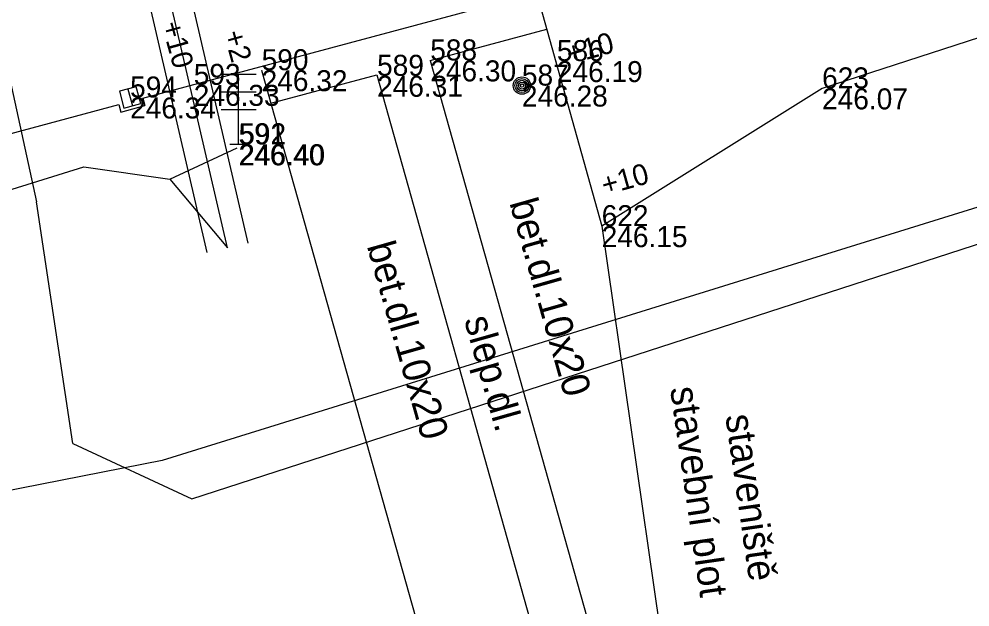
# Model space of a CAD drawing. Extents: x -599432 to -598680, y -1159407 to -1158632.
# Drawn here: x -599215.84 to -599202.25, y -1158968.08 to -1158959.67 of the extents above; entities that cross this region are included whole.
import ezdxf

# ---------------------------------------------------------------- set-up
doc = ezdxf.new("R2010")
doc.units = 0
for name, color, linetype in [('0004 VY - Body podrobné', 7, 'Continuous'), ('0005 VY - Body podrobné - čísla', 7, 'Continuous'), ('0006 VY - Body podrobné - výšky', 7, 'Continuous'), ('0015 ZA - Plot - kovový', 7, 'Continuous'), ('0026 ZA - Polohopis - buňky', 7, 'Continuous'), ('0027 ZA - Silnice_cesta zpevněná', 7, 'Continuous'), ('0030 ZA - Chodník', 7, 'Continuous'), ('0031 ZA - Ostatní rozhraní', 7, 'Continuous'), ('0032 TE - Popis povrchu', 7, 'Continuous'), ('0057 ZA - Doprava - BKOM buňky', 7, 'Continuous'), ('0073 TE - Výška obrubníků a zdí', 7, 'Continuous'), ('0074 TE - Vysvětlivky', 7, 'Continuous'), ('0075 ZA - BVK - kanalizace - buňky', 7, 'Continuous'), ('0552 PV - OT VUT', 7, 'Continuous'), ('0652 PV - BKOM - kabely bez rozlišení', 7, 'Continuous'), ('0653 PV - BKOM - chranička', 7, 'Continuous'), ('0700 PV - DIAL TELECOM - buňky', 7, 'Continuous'), ('0703 PV - DIAL TELECOM optický kabel', 7, 'Continuous')]:
    doc.layers.add(name, color=color, linetype=linetype)

msp = doc.modelspace()

# ---------------------------------------------------------------- linework, layer by layer
at = {"layer": '0004 VY - Body podrobné'}
for p, q in [((-599209.96, -1158960.26), (-599209.96, -1158960.26)), ((-599208.15, -1158960.27), (-599208.15, -1158960.27)), ((-599212.37, -1158960.4), (-599212.37, -1158960.4)), ((-599210.72, -1158960.48), (-599210.72, -1158960.48)), ((-599213.34, -1158960.61), (-599213.34, -1158960.61)), ((-599208.65, -1158960.62), (-599208.65, -1158960.62)), ((-599204.36, -1158960.66), (-599204.36, -1158960.66)), ((-599214.25, -1158960.79), (-599214.25, -1158960.79)), ((-599212.7, -1158961.46), (-599212.7, -1158961.46)), ((-599212.69, -1158961.46), (-599212.69, -1158961.46)), ((-599207.51, -1158962.63), (-599207.51, -1158962.63))]:
    msp.add_line(p, q, dxfattribs=at)
at = {"layer": '0015 ZA - Plot - kovový'}
for p, q in [((-599184.34, -1158954.17), (-599204.36, -1158960.66)), ((-599204.36, -1158960.66), (-599207.51, -1158962.63)), ((-599207.51, -1158962.63), (-599206.47, -1158969.84))]:
    msp.add_line(p, q, dxfattribs=at)
at = {"layer": '0026 ZA - Polohopis - buňky'}
for radius in [0.125, 0.1, 0.075, 0.05, 0.025]:
    msp.add_circle((-599208.65, -1158960.62), radius, dxfattribs=at)
at = {"layer": '0027 ZA - Silnice_cesta zpevněná'}
for p, q in [((-599214.067, -1158960.799), (-599208.44, -1158959.29)), ((-599208.44, -1158959.29), (-599207.51, -1158962.63)), ((-599217.91, -1158961.83), (-599214.411, -1158960.891)), ((-599214.411, -1158960.891), (-599214.382, -1158960.998)), ((-599214.382, -1158960.998), (-599214.038, -1158960.906)), ((-599214.067, -1158960.799), (-599214.038, -1158960.906))]:
    msp.add_line(p, q, dxfattribs=at)
at = {"layer": '0030 ZA - Chodník'}
msp.add_line((-599212.37, -1158960.4), (-599210.055, -1158968.634), dxfattribs=at)
at = {"layer": '0031 ZA - Ostatní rozhraní'}
for p, q in [((-599209.96, -1158960.26), (-599208.294, -1158959.813)), ((-599209.96, -1158960.26), (-599207.207, -1158970.052)), ((-599212.238, -1158960.871), (-599210.724, -1158960.465)), ((-599210.724, -1158960.465), (-599207.967, -1158970.271))]:
    msp.add_line(p, q, dxfattribs=at)
at = {"layer": '0057 ZA - Doprava - BKOM buňky'}
for p, q in [((-599212.45, -1158960.46), (-599212.95, -1158960.46)), ((-599212.7, -1158961.46), (-599212.7, -1158960.46)), ((-599212.95, -1158960.71), (-599212.45, -1158960.71)), ((-599212.95, -1158960.96), (-599212.45, -1158960.96)), ((-599212.825, -1158961.46), (-599212.575, -1158961.46))]:
    msp.add_line(p, q, dxfattribs=at)
at = {"layer": '0075 ZA - BVK - kanalizace - buňky'}
msp.add_line((-599214.283, -1158960.669), (-599214.217, -1158960.911), dxfattribs=at)
msp.add_lwpolyline([(-599214.403, -1158960.702), (-599214.338, -1158960.943), (-599214.097, -1158960.878), (-599214.162, -1158960.637)], close=True, dxfattribs=at)
at = {"layer": '0552 PV - OT VUT'}
msp.add_lwpolyline([(-599143.93, -1158953.57), (-599144.69, -1158954.41), (-599146.47, -1158953.73), (-599147.68, -1158952.78), (-599149.02, -1158951.66), (-599152.03, -1158949.46), (-599153.86, -1158948.56), (-599170.02, -1158952.91), (-599170.37, -1158953.05), (-599171.41, -1158953.39), (-599171.96, -1158953.52), (-599179.81, -1158955.74), (-599197.67, -1158960.97), (-599213.79, -1158965.98), (-599220.14, -1158967.23), (-599233.22, -1158970.89), (-599235.11, -1158971.48), (-599236.2, -1158971.2), (-599236.635, -1158972.68)], dxfattribs=at)
msp.add_lwpolyline([(-599143.93, -1158953.57), (-599144.69, -1158954.41), (-599146.47, -1158953.73), (-599147.68, -1158952.78), (-599149.02, -1158951.66), (-599152.03, -1158949.46), (-599153.86, -1158948.56), (-599170.02, -1158952.91), (-599170.37, -1158953.05), (-599171.41, -1158953.39), (-599171.96, -1158953.52), (-599179.81, -1158955.74), (-599197.67, -1158960.97), (-599213.79, -1158965.98), (-599220.14, -1158967.23), (-599233.22, -1158970.89), (-599235.11, -1158971.48), (-599236.2, -1158971.2), (-599236.635, -1158972.68)], dxfattribs=at)
at = {"layer": '0652 PV - BKOM - kabely bez rozlišení'}
msp.add_line((-599213.68, -1158961.96), (-599212.72, -1158961.51), dxfattribs=at)
for points in [[(-599230.59, -1158974.37), (-599220.8, -1158971.75), (-599221.6, -1158968.7), (-599221.47, -1158967), (-599221.32, -1158965.59), (-599219.76, -1158963.71), (-599218.51, -1158962.9), (-599214.91, -1158961.78), (-599213.68, -1158961.96), (-599212.86, -1158962.94), (-599216.66, -1158946.55), (-599217.48, -1158945.68), (-599223.02, -1158942.57)], [(-599234.98, -1158975.02), (-599233.92, -1158975.36), (-599230.92, -1158974.46), (-599230.59, -1158974.37), (-599220.8, -1158971.75), (-599221.6, -1158968.7), (-599221.47, -1158967), (-599221.32, -1158965.59), (-599219.76, -1158963.71), (-599218.51, -1158962.9), (-599214.91, -1158961.78), (-599213.68, -1158961.96), (-599212.86, -1158962.94), (-599216.66, -1158946.55), (-599215.68, -1158946.71), (-599213.41, -1158947.28), (-599210.22, -1158947.13), (-599194.67, -1158942.89)]]:
    msp.add_lwpolyline(points, dxfattribs=at)
at = {"layer": '0653 PV - BKOM - chranička'}
for p, q in [((-599216.368, -1158946.482), (-599212.568, -1158962.872)), ((-599216.952, -1158946.618), (-599213.152, -1158963.008))]:
    msp.add_line(p, q, dxfattribs=at)
at = {"layer": '0700 PV - DIAL TELECOM - buňky'}
msp.add_line((-599215.07, -1158965.74), (-599215.59, -1158962.28), dxfattribs=at)
at = {"layer": '0703 PV - DIAL TELECOM optický kabel'}
msp.add_line((-599215.07, -1158965.74), (-599215.59, -1158962.28), dxfattribs=at)
for points in [[(-599215.74, -1158938.78), (-599216.44, -1158939.68), (-599216.81, -1158942.07), (-599217.62, -1158947.51), (-599217.43, -1158950.41), (-599217.35, -1158953.4), (-599217.13, -1158956.4), (-599216.38, -1158958.66), (-599215.59, -1158962.28)], [(-599215.07, -1158965.74), (-599213.37, -1158966.53), (-599213.37, -1158966.53), (-599197.55, -1158961.4), (-599197.55, -1158961.4), (-599179.78, -1158956.07), (-599179.78, -1158956.07)], [(-599215.07, -1158965.74), (-599213.37, -1158966.53), (-599213.37, -1158966.53), (-599197.55, -1158961.4), (-599197.55, -1158961.4), (-599179.78, -1158956.07), (-599179.78, -1158956.07)]]:
    msp.add_lwpolyline(points, dxfattribs=at)

# ---------------------------------------------------------------- texts
at = {"layer": '0005 VY - Body podrobné - čísla'}
for s, p in [('588', (-599209.96, -1158960.26)), ('586', (-599208.15, -1158960.27)), ('590', (-599212.37, -1158960.4)), ('589', (-599210.72, -1158960.48)), ('593', (-599213.34, -1158960.61)), ('587', (-599208.65, -1158960.62)), ('623', (-599204.36, -1158960.66)), ('594', (-599214.25, -1158960.79)), ('591', (-599212.7, -1158961.46)), ('592', (-599212.69, -1158961.46)), ('622', (-599207.51, -1158962.63))]:
    msp.add_text(s, height=0.3, dxfattribs=at).set_placement(p)
at = {"layer": '0006 VY - Body podrobné - výšky'}
for s, p in [('246.30', (-599209.96, -1158960.56)), ('246.19', (-599208.15, -1158960.57)), ('246.32', (-599212.37, -1158960.7)), ('246.31', (-599210.72, -1158960.78)), ('246.33', (-599213.34, -1158960.91)), ('246.28', (-599208.65, -1158960.92)), ('246.07', (-599204.36, -1158960.96)), ('246.34', (-599214.25, -1158961.09)), ('246.40', (-599212.7, -1158961.76)), ('246.40', (-599212.69, -1158961.76)), ('246.15', (-599207.51, -1158962.93))]:
    msp.add_text(s, height=0.3, dxfattribs=at).set_placement(p)
at = {"layer": '0032 TE - Popis povrchu'}
for s, p in [('bet.dl.10x20', (-599208.831, -1158962.294)), ('bet.dl.10x20', (-599210.868, -1158962.911)), ('slep.dl.', (-599209.479, -1158963.968))]:
    msp.add_text(s, height=0.4, rotation=285.8481, dxfattribs=at).set_placement(p)
at = {"layer": '0073 TE - Výška obrubníků a zdí'}
for s, rotation, p in [('+10', 285.5595, (-599213.805, -1158959.743)), ('+2', 285.5595, (-599212.917, -1158959.871)), ('+10', 15.5595, (-599207.967, -1158960.32)), ('+10', 15.5595, (-599207.467, -1158962.193))]:
    msp.add_text(s, height=0.3, rotation=rotation, dxfattribs=at).set_placement(p)
at = {"layer": '0074 TE - Vysvětlivky'}
for s, p in [('stavební plot', (-599206.533, -1158964.948)), ('staveniště', (-599205.743, -1158965.343))]:
    msp.add_text(s, height=0.4, rotation=278.208, dxfattribs=at).set_placement(p)

doc.saveas('drawing.dxf')
